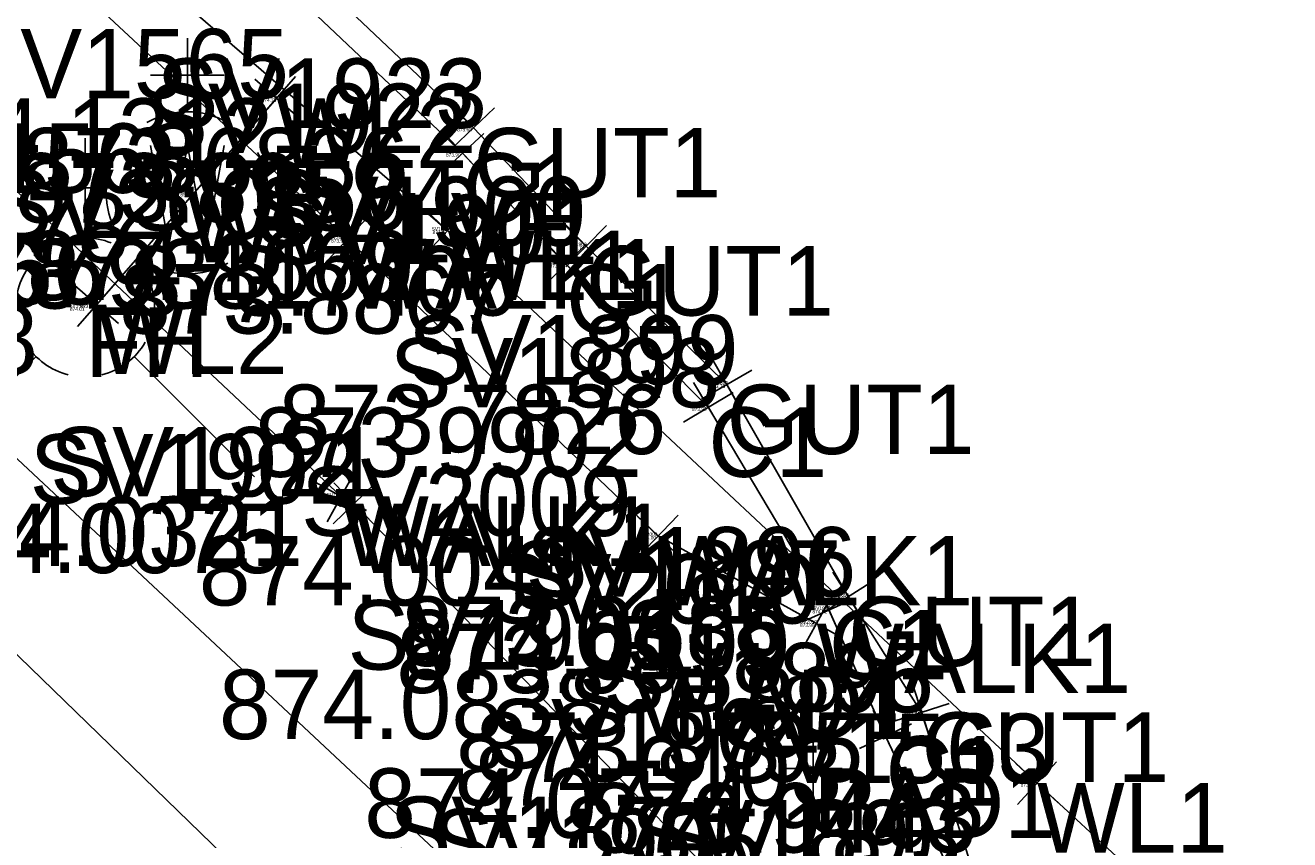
# Model space of a CAD drawing. Extents: x 1469677 to 1493262, y 375219 to 389293.
# Drawn here: x 1480127.45 to 1480149.29, y 379420.04 to 379434.1 of the extents above; entities that cross this region are included whole.
import ezdxf

# ---------------------------------------------------------------- set-up
doc = ezdxf.new("R2010")
doc.units = 0
for name, color, linetype in [('DR_X_Drive_Pipe', 7, 'Continuous'), ('DV_X_Lot_Line', 7, 'Continuous'), ('DV_X_Text', 7, 'Continuous'), ('GK_Visualization', 7, 'Continuous'), ('PNTELEV', 7, 'Continuous'), ('PNTNO', 7, 'Continuous'), ('RD_P_Text', 7, 'Continuous'), ('RW_P_Esmt_SW', 7, 'Continuous'), ('SV_X_Mon_Cells_Found', 7, 'Continuous'), ('text', 7, 'Continuous')]:
    doc.layers.add(name, color=color, linetype=linetype)

msp = doc.modelspace()

# ---------------------------------------------------------------- linework, layer by layer
at = {"layer": 'DR_X_Drive_Pipe'}
for points in [[(1480327.263, 379249.797), (1480312.798, 379263.799), (1480291.915, 379283.182), (1480274.385, 379298.987), (1480265.401, 379307.725), (1480264.495, 379308.458), (1480240.472, 379331.084), (1480234.677, 379335.863), (1480225.088, 379345.601), (1480208.322, 379361.342), (1480207.346, 379362.25), (1480199.528, 379369.768), (1480193.21, 379375.651), (1480182.823, 379385.139), (1480177.927, 379389.525), (1480169.423, 379398.321), (1480161.035, 379406.189), (1480144.924, 379421.019), (1480134.739, 379430.559), (1480121.485, 379441.998)], [(1480131.786, 379432.843), (1480128.679, 379429.282)]]:
    msp.add_lwpolyline(points, dxfattribs=at)
at = {"layer": 'DV_X_Lot_Line'}
for points in [[(1480106.316, 379456.227), (1480120.51, 379442.034), (1480133.01, 379430.413), (1480138.38, 379425.286), (1480141.112, 379423.774)], [(1480035.484, 379289.224), (1480050.568, 379305.437), (1480062.335, 379317.896), (1480064.038, 379319.719), (1480070.805, 379327.066), (1480078.054, 379334.946), (1480079.953, 379336.866), (1480094.208, 379352.393), (1480112.048, 379371.575), (1480117.348, 379377.211), (1480119.911, 379379.906), (1480121.511, 379381.77), (1480134.604, 379395.58), (1480136.695, 379398.148), (1480138.778, 379401.149), (1480140.004, 379404.725), (1480140.577, 379408.06), (1480140.982, 379411.311), (1480140.871, 379414.584), (1480140.225, 379417.636), (1480139.184, 379419.586), (1480133.124, 379425.845), (1480132.903, 379425.968), (1480114.834, 379442.96)]]:
    msp.add_lwpolyline(points, dxfattribs=at)
at = {"layer": 'PNTELEV'}
for p, q in [((1480132.163, 379432.515), (1480131.409, 379433.172)), ((1480132.115, 379433.22), (1480131.457, 379432.467)), ((1480131.786, 379432.843), (1480131.786, 379432.843)), ((1480134.828, 379431.987), (1480135.552, 379432.677)), ((1480135.535, 379431.97), (1480134.845, 379432.694)), ((1480134.634, 379431.556), (1480135.366, 379432.238)), ((1480135.341, 379431.531), (1480134.659, 379432.263)), ((1480135.19, 379432.332), (1480135.19, 379432.332)), ((1480135, 379431.897), (1480135, 379431.897)), ((1480135.104, 379430.217), (1480134.374, 379430.901)), ((1480134.397, 379430.194), (1480135.081, 379430.924)), ((1480132.644, 379430.754), (1480133.376, 379430.073)), ((1480133.35, 379430.779), (1480132.67, 379430.047)), ((1480137.489, 379429.942), (1480136.777, 379430.643)), ((1480136.782, 379429.936), (1480137.484, 379430.649)), ((1480133.01, 379430.413), (1480133.01, 379430.413)), ((1480134.739, 379430.559), (1480134.739, 379430.559)), ((1480136.432, 379429.627), (1480137.142, 379430.332)), ((1480137.14, 379429.625), (1480136.434, 379430.334)), ((1480137.133, 379430.292), (1480137.133, 379430.292)), ((1480136.787, 379429.98), (1480136.787, 379429.98)), ((1480129.055, 379428.953), (1480128.302, 379429.61)), ((1480129.007, 379429.658), (1480128.35, 379428.905)), ((1480128.679, 379429.282), (1480128.679, 379429.282)), ((1480139.813, 379427.466), (1480139.315, 379428.334)), ((1480139.13, 379427.651), (1480139.998, 379428.149)), ((1480139.503, 379427.077), (1480138.991, 379427.936)), ((1480139.564, 379427.9), (1480139.564, 379427.9)), ((1480138.817, 379427.25), (1480139.677, 379427.762)), ((1480139.247, 379427.506), (1480139.247, 379427.506)), ((1480132.66, 379425.531), (1480133.146, 379426.405)), ((1480133.34, 379425.725), (1480132.466, 379426.211)), ((1480132.765, 379425.497), (1480133.483, 379426.193)), ((1480133.472, 379425.486), (1480132.776, 379426.204)), ((1480132.903, 379425.968), (1480132.903, 379425.968)), ((1480133.124, 379425.845), (1480133.124, 379425.845)), ((1480138.018, 379425.631), (1480138.742, 379424.94)), ((1480138.725, 379425.647), (1480138.035, 379424.924)), ((1480138.38, 379425.286), (1480138.38, 379425.286)), ((1480141.242, 379423.973), (1480142.086, 379424.507)), ((1480141.931, 379423.818), (1480141.397, 379424.663)), ((1480141.535, 379423.552), (1480141.125, 379424.465)), ((1480141.354, 379424.211), (1480140.87, 379423.336)), ((1480140.874, 379423.804), (1480141.786, 379424.213)), ((1480141.664, 379424.24), (1480141.664, 379424.24)), ((1480140.675, 379424.016), (1480141.549, 379423.532)), ((1480141.33, 379424.009), (1480141.33, 379424.009)), ((1480141.112, 379423.774), (1480141.112, 379423.774)), ((1480138.625, 379423.478), (1480138.625, 379422.478)), ((1480138.125, 379422.978), (1480139.125, 379422.978)), ((1480138.625, 379422.978), (1480138.625, 379422.978)), ((1480143.084, 379421.764), (1480142.776, 379422.715)), ((1480142.454, 379422.086), (1480143.406, 379422.393)), ((1480142.522, 379421.379), (1480142.092, 379422.281)), ((1480142.93, 379422.24), (1480142.93, 379422.24)), ((1480141.856, 379421.615), (1480142.758, 379422.045)), ((1480141.058, 379421.773), (1480141.058, 379420.773)), ((1480142.307, 379421.83), (1480142.307, 379421.83)), ((1480140.558, 379421.273), (1480141.558, 379421.273)), ((1480141.058, 379421.273), (1480141.058, 379421.273)), ((1480145.292, 379420.68), (1480144.556, 379421.358)), ((1480144.585, 379420.651), (1480145.262, 379421.387)), ((1480144.924, 379421.019), (1480144.924, 379421.019))]:
    msp.add_line(p, q, dxfattribs=at)
at = {"layer": 'PNTNO'}
for p, q in [((1480130.245, 379432.61), (1480130.245, 379433.881)), ((1480130.88, 379433.246), (1480129.608, 379433.246)), ((1480128.478, 379430.438), (1480128.478, 379432.158)), ((1480129.678, 379431.298), (1480127.278, 379431.298)), ((1480130.245, 379431.21), (1480130.245, 379431.21)), ((1480128.48, 379429.234), (1480128.48, 379429.234)), ((1480128.48, 379429.234), (1480128.48, 379429.234)), ((1480127.633, 379428.386), (1480125.553, 379426.308)), ((1480129.325, 379428.386), (1480131.405, 379426.308))]:
    msp.add_line(p, q, dxfattribs=at)
msp.add_lwpolyline([(1480129.608, 379432.03), (1480129.927, 379430.306), (1480130.245, 379432.03), (1480130.565, 379430.306), (1480130.882, 379432.03)], dxfattribs=at)
for centre, radius, start, end in [((1480130.244, 379431.211), 1.4, 60.0184, 120.0157), ((1480130.244, 379431.211), 1.4, 150.0184, 209.9816), ((1480130.244, 379431.211), 1.4, 330.0184, 29.9816), ((1480128.48, 379429.234), 1.2, 68.1395, 112.038), ((1480128.48, 379429.234), 1.2, 140.021, 184.0629), ((1480128.48, 379429.234), 1.2, 356.0165, 39.9889), ((1480130.244, 379431.211), 1.4, 239.9843, 299.9816), ((1480128.48, 379429.234), 1.2, 211.8788, 255.8479), ((1480128.48, 379429.234), 1.2, 283.8239, 329.9097)]:
    msp.add_arc(centre, radius, start, end, dxfattribs=at)
at = {"layer": 'RD_P_Text'}
for points in [[(1480082.794, 379333.357), (1480097.622, 379349.287), (1480115.163, 379368.135), (1480120.989, 379374.507), (1480122.913, 379376.573), (1480123.248, 379376.579), (1480124.233, 379378.045), (1480138.666, 379393.676), (1480140.342, 379395.44), (1480142.173, 379398.797), (1480143.522, 379402.786), (1480144.219, 379407.995), (1480144.4, 379409.609), (1480144.536, 379411.589), (1480144.804, 379414.142), (1480144.365, 379416.981), (1480143.824, 379419.476), (1480142.93, 379422.24), (1480141.664, 379424.24), (1480139.564, 379427.9), (1480137.133, 379430.292), (1480135.19, 379432.332), (1480118.45, 379448.16)], [(1480082.529, 379333.877), (1480097.272, 379349.731), (1480114.906, 379368.678), (1480120.582, 379374.885), (1480122.682, 379377.153), (1480124.005, 379378.548), (1480138.475, 379394.29), (1480139.717, 379395.951), (1480141.648, 379398.861), (1480143.063, 379403.22), (1480143.762, 379408.065), (1480143.873, 379409.698), (1480144.124, 379411.499), (1480144.338, 379414.245), (1480144.085, 379416.674), (1480143.405, 379419.529), (1480142.307, 379421.83), (1480141.33, 379424.009), (1480139.247, 379427.506), (1480136.787, 379429.98), (1480135, 379431.897), (1480118.039, 379447.914)]]:
    msp.add_lwpolyline(points, dxfattribs=at)
at = {"layer": 'SV_X_Mon_Cells_Found'}
msp.add_lwpolyline([(1477164.629, 382297.849), (1479615.888, 379904.59), (1480413.414, 379159.216)], dxfattribs=at)
at = {"layer": 'text'}
msp.add_lwpolyline([(1480127.721, 379395.358), (1480131.799, 379398.039), (1480133.273, 379401.352), (1480135.459, 379407.36), (1480135.6, 379409.555), (1480135.793, 379413.076), (1480135.014, 379415.657), (1480133.026, 379417.684), (1480123.803, 379426.624), (1480113.121, 379435.343), (1480106.984, 379440.926), (1480103.73, 379443.918), (1480102.529, 379445.074), (1480100.774, 379445.951), (1480096.595, 379444.059), (1480092.174, 379441.029), (1480086.377, 379436.591)], dxfattribs=at)

# ---------------------------------------------------------------- texts
at = {"layer": 'DV_X_Text'}
for s, height, p in [('874.1312', 1.2, (1480125.032, 379431.643)), ('874.13', 0.06, (1480131.529, 379432.783)), ('873.6836', 1.2, (1480127.376, 379431.132)), ('873.68', 0.06, (1480134.907, 379432.272)), ('873.8959', 1.2, (1480127.271, 379430.697)), ('873.90', 0.06, (1480134.713, 379431.837)), ('873.8478', 1.2, (1480122.545, 379430.01)), ('873.85', 0.06, (1480129.964, 379431.15)), ('873.9381', 1.2, (1480125.723, 379429.213)), ('874.1669', 1.2, (1480127.474, 379429.359)), ('873.94', 0.06, (1480132.728, 379430.353)), ('874.17', 0.06, (1480134.482, 379430.499)), ('873.7406', 1.2, (1480129.253, 379429.092)), ('873.74', 0.06, (1480136.853, 379430.232)), ('873.8867', 1.2, (1480129.068, 379428.78)), ('873.89', 0.06, (1480136.505, 379429.92)), ('873.9758', 1.2, (1480120.969, 379428.082)), ('874.01', 0.06, (1480128.216, 379429.174)), ('873.98', 0.06, (1480128.396, 379429.222)), ('873.7826', 1.2, (1480131.826, 379426.7)), ('873.78', 0.06, (1480139.283, 379427.84)), ('873.9902', 1.2, (1480131.405, 379426.306)), ('873.99', 0.06, (1480138.964, 379427.446)), ('874.0075', 1.2, (1480125.225, 379424.645)), ('874.0321', 1.2, (1480125.55, 379424.768)), ('874.03', 0.06, (1480132.617, 379425.908)), ('874.01', 0.06, (1480132.86, 379425.785)), ('874.0049', 1.2, (1480130.444, 379424.086)), ('874.00', 0.06, (1480138.089, 379425.226)), ('873.8685', 1.2, (1480133.945, 379423.04)), ('873.87', 0.06, (1480141.383, 379424.18)), ('874.0199', 1.2, (1480133.97, 379422.809)), ('874.02', 0.06, (1480141.044, 379423.949)), ('873.9818', 1.2, (1480133.856, 379422.574)), ('873.98', 0.06, (1480140.829, 379423.714)), ('874.0838', 1.2, (1480130.792, 379421.778)), ('874.08', 0.06, (1480138.338, 379422.918)), ('873.8795', 1.2, (1480135.23, 379421.04)), ('873.88', 0.06, (1480142.648, 379422.18)), ('874.0103', 1.2, (1480134.863, 379420.63)), ('874.01', 0.06, (1480142.043, 379421.77)), ('874.0774', 1.2, (1480133.301, 379420.073)), ('874.08', 0.06, (1480140.771, 379421.213)), ('873.9443', 1.2, (1480137.186, 379419.819)), ('873.94', 0.06, (1480144.642, 379420.959))]:
    msp.add_text(s, height=height, dxfattribs=at).set_placement(p)
at = {"layer": 'GK_Visualization'}
for s, p in [('WL2', (1480131.786, 379431.643)), ('GUT1', (1480135.19, 379431.132)), ('C1', (1480135, 379430.697)), ('WVALVE', (1480130.245, 379430.01)), ('WALK1', (1480133.01, 379429.213)), ('WL1', (1480134.739, 379429.359)), ('GUT1', (1480137.133, 379429.092)), ('C1', (1480136.787, 379428.78)), ('FH', (1480128.48, 379428.034)), ('WL2', (1480128.679, 379428.082)), ('GUT1', (1480139.564, 379426.7)), ('C1', (1480139.247, 379426.306)), ('WALK1', (1480132.903, 379424.768)), ('WALK1', (1480133.124, 379424.645)), ('WALK1', (1480138.38, 379424.086)), ('GUT1', (1480141.664, 379423.04)), ('C1', (1480141.33, 379422.809)), ('WALK1', (1480141.112, 379422.574)), ('PAD1', (1480138.625, 379421.778)), ('GUT1', (1480142.93, 379421.04)), ('C1', (1480142.307, 379420.63)), ('PAD1', (1480141.058, 379420.073)), ('WL1', (1480144.924, 379419.819))]:
    msp.add_text(s, height=1.2, dxfattribs=at).set_placement(p)
at = {"layer": 'RW_P_Esmt_SW'}
for s, height, p in [('SV1565', 1.2, (1480126.288, 379432.843)), ('SV1923', 1.2, (1480129.711, 379432.332)), ('SV1922', 1.2, (1480129.53, 379431.897)), ('SV1565', 0.06, (1480131.511, 379432.843)), ('SV1568', 1.2, (1480124.737, 379431.21)), ('SV1923', 0.06, (1480134.916, 379432.332)), ('SV1922', 0.06, (1480134.727, 379431.897)), ('SV1564', 1.2, (1480129.251, 379430.559)), ('SV2008', 1.2, (1480126.84, 379430.413)), ('SV1900', 1.2, (1480131.417, 379430.292)), ('SV1568', 0.06, (1480129.97, 379431.21)), ('SV1901', 1.2, (1480131.627, 379429.98)), ('SV1564', 0.06, (1480134.465, 379430.559)), ('SV1567', 1.2, (1480122.982, 379429.234)), ('SV1566', 1.2, (1480123.105, 379429.282)), ('SV2008', 0.06, (1480132.702, 379430.413)), ('SV1900', 0.06, (1480136.847, 379430.292)), ('SV1901', 0.06, (1480136.529, 379429.98)), ('SV1566', 0.06, (1480128.4, 379429.282)), ('SV1567', 0.06, (1480128.205, 379429.234)), ('SV1899', 1.2, (1480134.056, 379427.9)), ('SV1898', 1.2, (1480133.739, 379427.506)), ('SV1899', 0.06, (1480139.289, 379427.9)), ('SV1898', 0.06, (1480138.972, 379427.506)), ('SV1921', 1.2, (1480127.875, 379425.968)), ('SV1902', 1.2, (1480127.522, 379425.845)), ('SV2009', 1.2, (1480132.21, 379425.286)), ('SV1921', 0.06, (1480132.652, 379425.968)), ('SV1902', 0.06, (1480132.844, 379425.845)), ('SV1896', 1.2, (1480136.09, 379424.24)), ('SV1897', 1.2, (1480135.832, 379424.009)), ('SV2009', 0.06, (1480138.072, 379425.286)), ('SV2010', 1.2, (1480135.434, 379423.774)), ('SV1896', 0.06, (1480141.385, 379424.24)), ('SV1903', 1.2, (1480133.013, 379422.978)), ('SV1897', 0.06, (1480141.055, 379424.009)), ('SV2010', 0.06, (1480140.828, 379423.774)), ('SV1895', 1.2, (1480137.432, 379422.24)), ('SV1894', 1.2, (1480136.818, 379421.83)), ('SV1903', 0.06, (1480138.344, 379422.978)), ('SV1904', 1.2, (1480135.456, 379421.273)), ('SV1563', 1.2, (1480139.426, 379421.019)), ('SV1895', 0.06, (1480142.655, 379422.24)), ('SV1894', 0.06, (1480142.033, 379421.83)), ('SV1904', 0.06, (1480140.778, 379421.273)), ('SV1563', 0.06, (1480144.649, 379421.019)), ('SV1874', 1.2, (1480133.733, 379419.586)), ('SV1905', 1.2, (1480134.467, 379419.378)), ('SV1893', 1.2, (1480137.907, 379419.529)), ('SV1892', 1.2, (1480138.335, 379419.476))]:
    msp.add_text(s, height=height, dxfattribs=at).set_placement(p)

doc.saveas('drawing.dxf')
